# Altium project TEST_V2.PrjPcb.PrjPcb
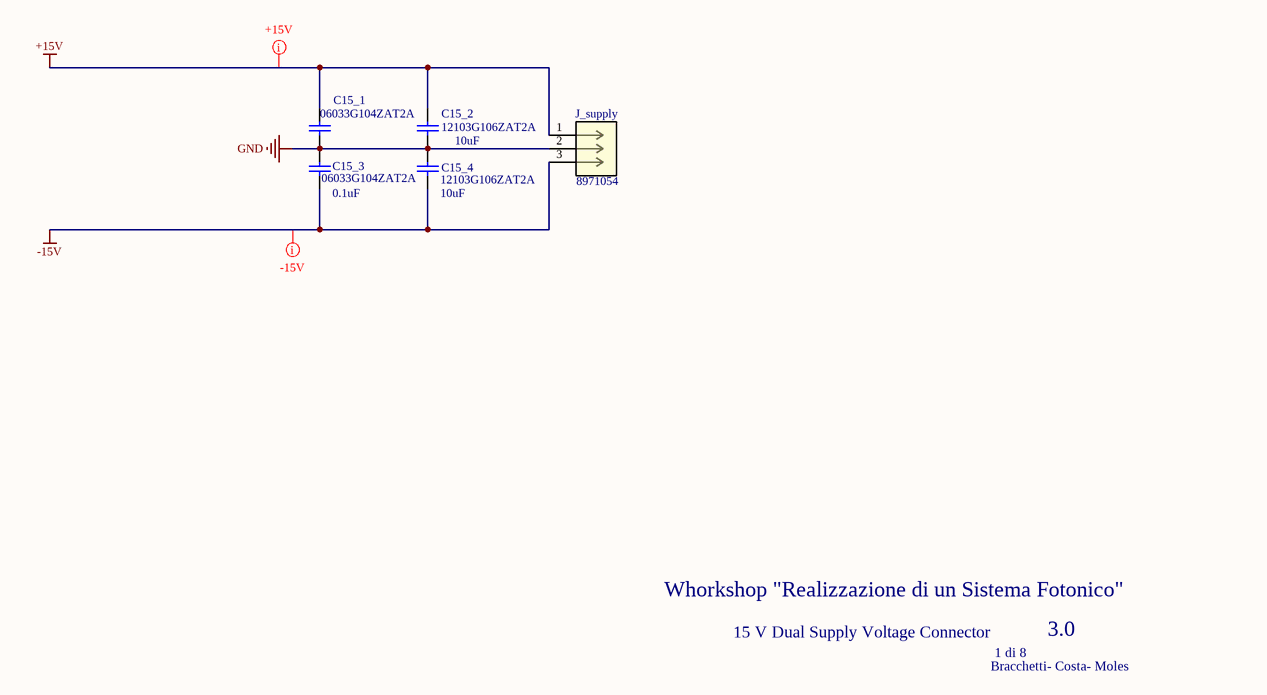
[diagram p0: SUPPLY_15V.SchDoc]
8 sheets, 172 parts. Net scope: flat (ports and power ports of the same name join across sheets).
Board file: 6C-2L-1550um.PcbDoc
Sheets:
  SUPPLY_15V.SchDoc
  SUPPLY_3V3.SchDoc
  SUPPLY_5V.SchDoc
  STAGE _1_2.SchDoc
  SWITCH_stage.SchDoc
  Selector_stage.SchDoc
  Filters.SchDoc
  OUT_STAGE.SchDoc

## Sheet SUPPLY_15V.SchDoc
size A4

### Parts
C15_1  06033G104ZAT2A  [1608[0603]]
C15_2  12103G106ZAT2A  value 10uF  [C1210_M]
C15_3  06033G104ZAT2A  value 0.1uF  [1608[0603]]
C15_4  12103G106ZAT2A  value 10uF  [C1210_M]
J_supply  8971054  [CONN_8971054_RSP]

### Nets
+15V: C15_1.2 C15_2.2 J_supply.1
-15V: C15_3.1 C15_4.1 J_supply.3
GND: C15_1.1 C15_2.1 C15_3.2 C15_4.2 J_supply.2

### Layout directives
net class +15V: +15V
net class -15V: -15V

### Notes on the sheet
- Whorkshop "Realizzazione di un Sistema Fotonico"
- 15 V Dual Supply Voltage Connector
- 1 di 8
- 3.0
- Bracchetti- Costa- Moles

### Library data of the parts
C15_1 = Cap Semi: Capacitor (Semiconductor SIM Model); Value: 0.1uF
C15_2-C15_4 = Cap Semi: Capacitor (Semiconductor SIM Model)
J_supply = 8971054: No Description Available; Built_By: EMA_Justin; Vendor: RS PRO; SourceLibrary: RS_Pro_2020-07-29

## Sheet SUPPLY_3V3.SchDoc
size A4
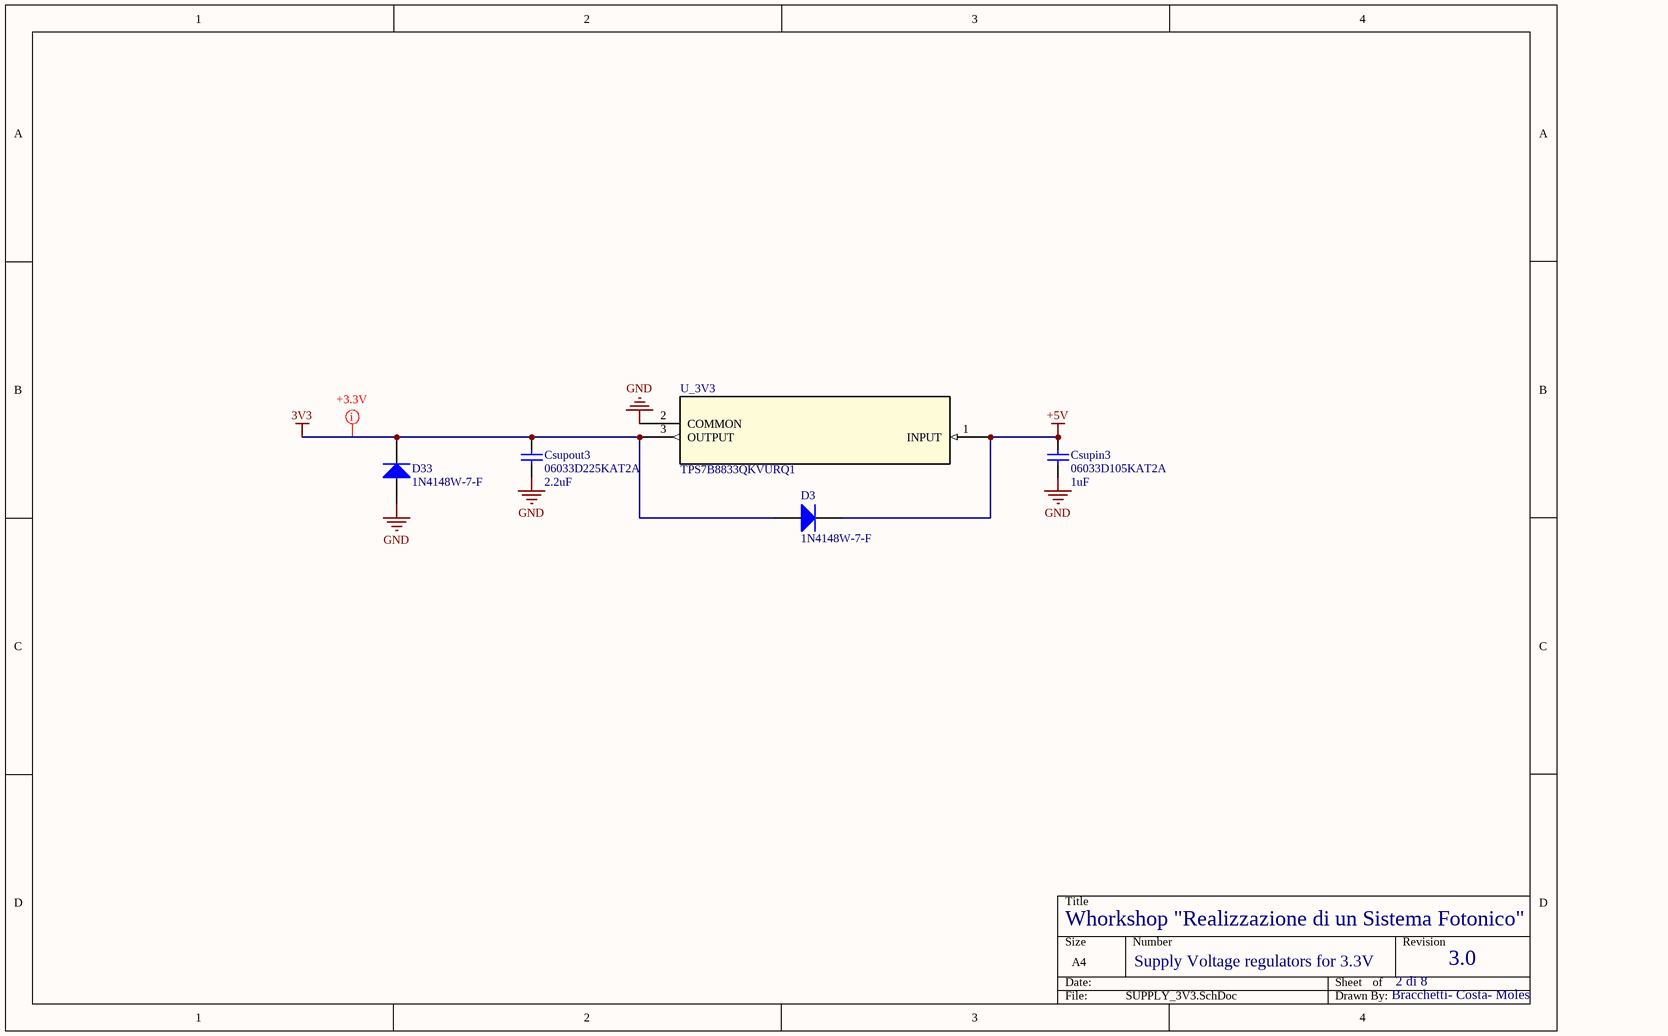
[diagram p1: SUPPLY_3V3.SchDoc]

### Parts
Csupin3  06033D105KAT2A  value 1uF  [1608[0603]]
Csupout3  06033D225KAT2A  value 2.2uF  [1608[0603]]
D3  1N4148W-7-F  [DIOD-SOD123-2_V]
D33  1N4148W-7-F  [DIOD-SOD123-2_V]
U_3V3  TPS7B8833QKVURQ1  [KVU3_TEX]

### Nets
3V3: Csupout3.2 D3.1(A) D33.2(K) U_3V3.3(OUTPUT)
+5V: Csupin3.2 D3.2(K) U_3V3.1(INPUT)
GND: Csupin3.1 Csupout3.1 D33.1(A) U_3V3.2(COMMON)

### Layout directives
net class 3.3V: 3V3

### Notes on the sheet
- Whorkshop "Realizzazione di un Sistema Fotonico"
- Supply Voltage regulators for 3.3V
- 2 di 8
- 3.0
- Bracchetti- Costa- Moles

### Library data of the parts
Csupin3 Csupout3 = Cap Semi: Capacitor (Semiconductor SIM Model)
D3 D33 = CMP-2000-04932-2: Fast Switching Diode, 100 V, 0.15 A, -65 to 150 degC, 2-Pin?SOD123, RoHS, Tape and Reel; Recovery Time: 4ns; Brand: DiodesIncorporated; Unit Weight: 0.000353oz; Max Surge Current: 2A; Peak Reverse Voltage: 100V; Ir - Reverse Current: 1uA; Vf - Forward Voltage: 1.25V; Configuration: Single; If - Forward Current: 0.15A
U_3V3 = UA78M33IKVURG3: No Description Available; Vendor: Texas Instruments; Built_By: EMA_UL_Team; SourceLibrary: TI_2016-07-22

## Sheet SUPPLY_5V.SchDoc
size A4
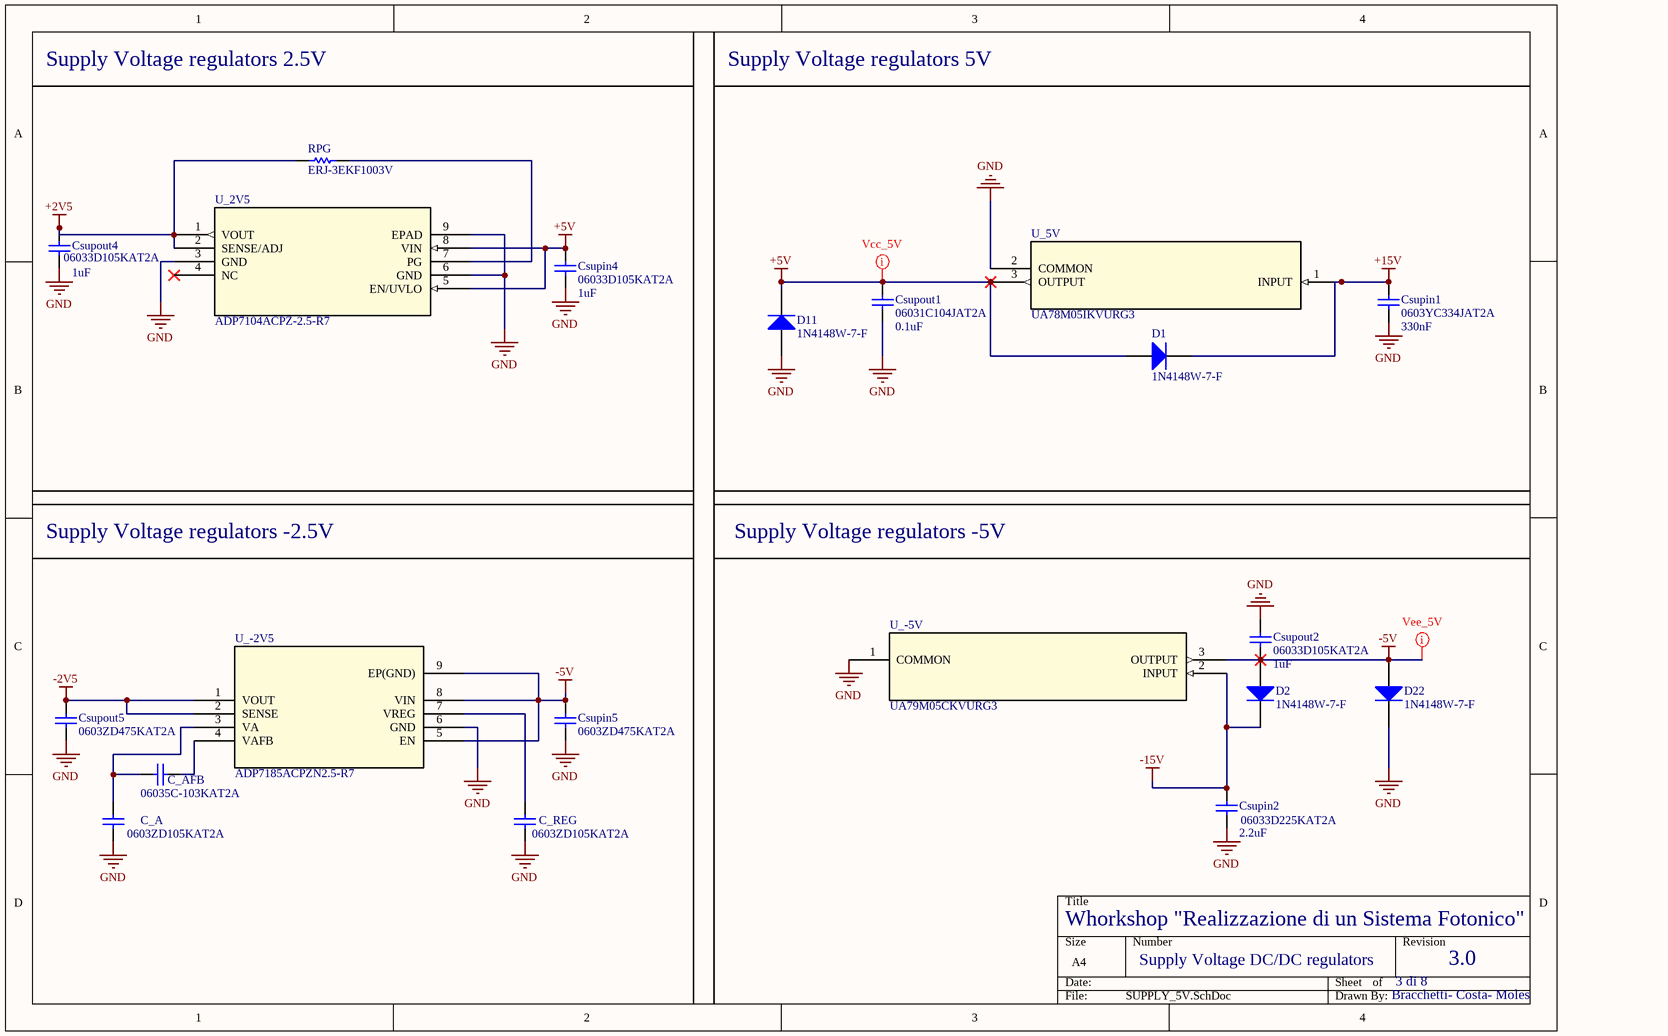
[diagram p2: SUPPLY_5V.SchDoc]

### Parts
C_A  0603ZD105KAT2A  [CAPC1608X86X35LL15T15]
C_AFB  06035C-103KAT2A  [CAPC1608X90X35LL15T15]
C_REG  0603ZD105KAT2A  [CAPC1608X86X35LL15T15]
Csupin1  0603YC334JAT2A  value 330nF  [1608[0603]]
Csupin2  06033D225KAT2A  value 2.2uF  [1608[0603]]
Csupin4  06033D105KAT2A  value 1uF  [1608[0603]]
Csupin5  0603ZD475KAT2A  [CAPC1608X90X35NL15T15]
Csupout1  06031C104JAT2A  value 0.1uF  [1608[0603]]
Csupout2  06033D105KAT2A  value 1uF  [1608[0603]]
Csupout4  06033D105KAT2A  value 1uF  [1608[0603]]
Csupout5  0603ZD475KAT2A  [CAPC1608X90X35NL15T15]
D1  1N4148W-7-F  [DIOD-SOD123-2_V]
D2  1N4148W-7-F  [DIOD-SOD123-2_V]
D11  1N4148W-7-F  [DIOD-SOD123-2_V]
D22  1N4148W-7-F  [DIOD-SOD123-2_V]
RPG  ERJ-3EKF1003V  [RESC1608X55X30ML15T15]
U_2V5  ADP7104ACPZ-2.5-R7  [CP_8_5_ADI]
U_5V  UA78M05IKVURG3  [KVU3_TEX]
U_-2V5  ADP7185ACPZN2.5-R7  [CP_8_27_ADI]
U_-5V  UA79M05CKVURG3  [KVU3_TEX]

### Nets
+2V5: Csupout4.2 RPG.2 U_2V5.1(VOUT) U_2V5.2(SENSE/ADJ)
+5V: Csupin4.2 Csupout1.2 D1.1(A) D11.2(K) U_2V5.5(EN/UVLO) U_2V5.8(VIN) U_5V.3(OUTPUT)
+15V: Csupin1.2 D1.2(K) U_5V.1(INPUT)
-2V5: Csupout5.2 U_-2V5.1(VOUT) U_-2V5.2(SENSE)
-5V: Csupin5.2 Csupout2.1 D2.1(A) D22.1(A) U_-2V5.5(EN) U_-2V5.8(VIN) U_-2V5.9(EP(GND)) U_-5V.3(OUTPUT)
-15V: Csupin2.2 D2.2(K) U_-5V.2(INPUT)
GND: C_A.1 C_REG.1 Csupin1.1 Csupin2.1 Csupin4.1 Csupin5.1 Csupout1.1 Csupout2.2 Csupout4.1 Csupout5.1 D11.1(A) D22.2(K) U_2V5.3(GND) U_2V5.6(GND) U_2V5.9(EPAD) U_5V.2(COMMON) U_-2V5.6(GND) U_-5V.1(COMMON)
NetC_A_2: C_A.2 C_AFB.2 U_-2V5.3(VA)
NetC_AFB_1: C_AFB.1 U_-2V5.4(VAFB)
NetC_REG_2: C_REG.2 U_-2V5.7(VREG)
NetRPG_1: RPG.1 U_2V5.7(PG)

Not connected (* = marked no-connect by the designer): U_2V5 4(NC)*

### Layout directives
net class +5V: +5V
net class -5V: -5V

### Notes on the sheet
- Supply Voltage regulators 2.5V
- Supply Voltage regulators 5V
- Supply Voltage regulators -2.5V
- Supply Voltage regulators -5V
- Whorkshop "Realizzazione di un Sistema Fotonico"
- Supply Voltage DC/DC regulators
- 3 di 8
- 3.0
- Bracchetti- Costa- Moles

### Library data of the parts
C_A C_REG = CMP-2006-04559-2: Chip Capacitor, 1 uF, +/- 10%, 10 V, -55 to 85 degC, 0603 (1608 Metric), RoHS, Tape and Reel; Manufacturer: AVX; Rated Voltage: 10V; Capacitance: 1µF; Dielectric: X5R
C_AFB = CMP-2006-04374-1: Manufacturer: AVX Interconnect / Elco
Csupin1 Csupin2 Csupin4 Csupout1 Csupout2 Csupout4 = Cap Semi: Capacitor (Semiconductor SIM Model)
Csupin5 Csupout5 = CMP-2006-04567-1: Manufacturer: AVX Interconnect / Elco
D1 D2 D11 D22 = CMP-2000-04932-2: as D3 on sheet SUPPLY_3V3
RPG = CMP-2000-00182-1: Manufacturer: Panasonic
U_2V5 = ADP7104ACPZ-2.5-R7: No Description Available; Vendor: Analog Devices Inc; Built_By: EMA_Christopher; SourceLibrary: Analog_Devices_2018-07-13
U_5V = UA78M05IKVURG3: No Description Available; Vendor: Texas Instruments; Built_By: EMA_UL_Team; SourceLibrary: TI_2016-07-22
U_-2V5 = ADP7185ACPZN2.5-R7: No Description Available; Vendor: Analog Devices Inc; Built_By: Analog Devices Inc.; SourceLibrary: Analog_2017-10-24
U_-5V = UA79M05CKVURG3: No Description Available; Vendor: Texas Instruments; Built_By: EMA_UL_Team; SourceLibrary: TI_2015-1-6

## Sheet STAGE _1_2.SchDoc
size A4
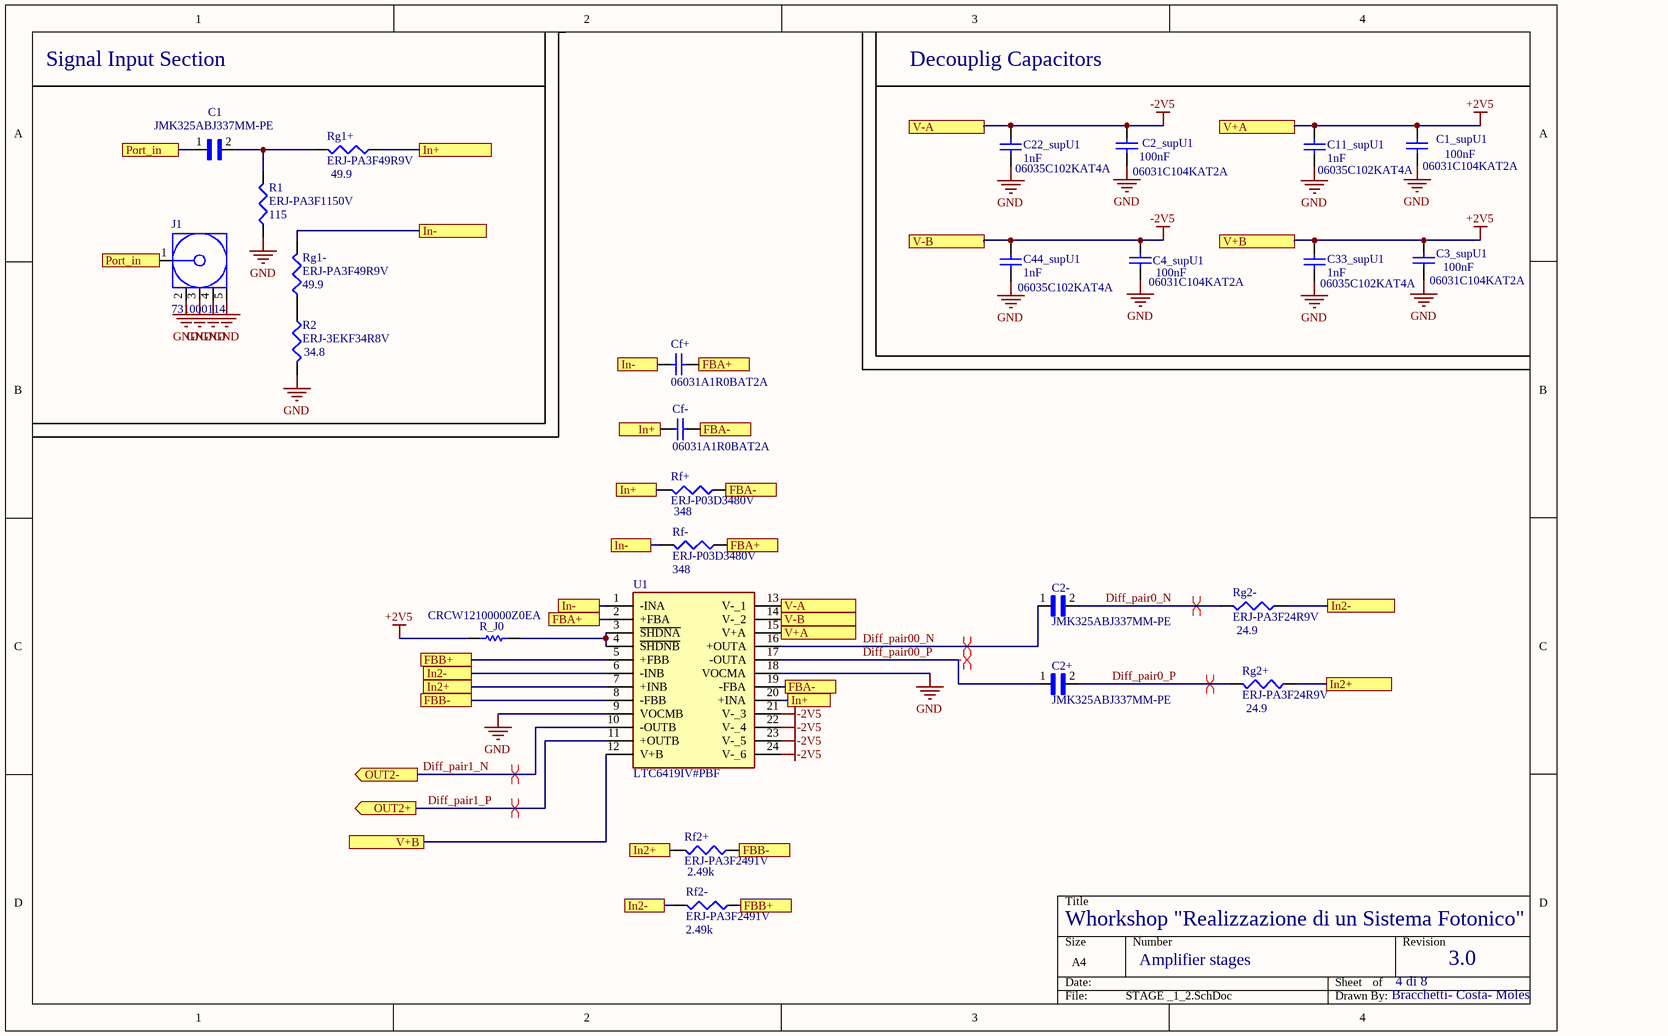
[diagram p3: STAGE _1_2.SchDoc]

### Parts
C1  JMK325ABJ337MM-PE  [CAPC3225X280N]
C1_supU1  06031C104KAT2A  value 100nF  [1608[0603]]
C2+  JMK325ABJ337MM-PE  [CAPC3225X280N]
C2-  JMK325ABJ337MM-PE  [CAPC3225X280N]
C2_supU1  06031C104KAT2A  value 100nF  [1608[0603]]
C3_supU1  06031C104KAT2A  value 100nF  [1608[0603]]
C4_supU1  06031C104KAT2A  value 100nF  [1608[0603]]
C11_supU1  06035C102KAT4A  value 1nF  [1608[0603]]
C22_supU1  06035C102KAT4A  value 1nF  [1608[0603]]
C33_supU1  06035C102KAT4A  value 1nF  [1608[0603]]
C44_supU1  06035C102KAT4A  value 1nF  [1608[0603]]
Cf+  06031A1R0BAT2A  [CAPC1608X90X35LL15T15]
Cf-  06031A1R0BAT2A  [CAPC1608X90X35LL15T15]
J1  731000114  [MOLX-731000114_V]
R1  ERJ-PA3F1150V  value 115  [1608[0603]]
R2  ERJ-3EKF34R8V  value 34.8  [1608[0603]]
R_J0  CRCW12100000Z0EA  [RESC3225X60X45NL20T20]
Rf2+  ERJ-PA3F2491V  value 2.49k  [1608[0603]]
Rf2-  ERJ-PA3F2491V  value 2.49k  [1608[0603]]
Rf+  ERJ-P03D3480V  value 348  [1608[0603]]
Rf-  ERJ-P03D3480V  value 348  [1608[0603]]
Rg1+  ERJ-PA3F49R9V  value 49.9  [1608[0603]]
Rg1-  ERJ-PA3F49R9V  value 49.9  [1608[0603]]
Rg2+  ERJ-PA3F24R9V  value 24.9  [1608[0603]]
Rg2-  ERJ-PA3F24R9V  value 24.9  [1608[0603]]
U1  LTC6419IV#PBF  [LTC6419IVPBF]

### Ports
FBA+, FBA-, FBB+, FBB-, In2+, In2-, In+, In-, OUT2+ (out), OUT2- (out), Port_in, V+A, V+B, V-A, V-B

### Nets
+2V5: C1_supU1.1 C3_supU1.1 C11_supU1.1 C33_supU1.1 R_J0.1 U1.12(V+B) U1.15(V+A) ; port V+A, port V+B
-2V5: C2_supU1.1 C4_supU1.1 C22_supU1.1 C44_supU1.1 U1.13(V-_1) U1.14(V-_2) U1.21(V-_3) U1.22(V-_4) U1.23(V-_5) U1.24(V-_6) ; port V-A, port V-B
GND: C1_supU1.2 C2_supU1.2 C3_supU1.2 C4_supU1.2 C11_supU1.2 C22_supU1.2 C33_supU1.2 C44_supU1.2 J1.2 J1.3 J1.4 J1.5 R1.1 R2.2 U1.9(VOCMB) U1.18(VOCMA)
Diff_pair0_N: C2-.2 Rg2-.2
Diff_pair00_N: C2-.1 U1.16(+OUTA)
Diff_pair0_P: C2+.2 Rg2+.2
Diff_pair00_P: C2+.1 U1.17(-OUTA)
Diff_pair1_N: U1.10(-OUTB) ; port OUT2-
Diff_pair1_P: U1.11(+OUTB) ; port OUT2+
NetC1_1: C1.1 J1.1 ; port Port_in
NetC1_2: C1.2 R1.2 Rg1+.2
NetCf+_1: Cf+.1 Rf-.2 Rg1-.2 U1.1(-INA) ; port In-
NetCf+_2: Cf+.2 Rf-.1 U1.2(+FBA) ; port FBA+
NetCf-_1: Cf-.1 Rf+.2 Rg1+.1 U1.20(+INA) ; port In+
NetCf-_2: Cf-.2 Rf+.1 U1.19(-FBA) ; port FBA-
NetR2_1: R2.1 Rg1-.1
NetR_J0_2: R_J0.2 U1.3(~{SHDNA}) U1.4(~{SHDNB})
NetRf2+_1: Rf2+.1 U1.8(-FBB) ; port FBB-
NetRf2+_2: Rf2+.2 Rg2+.1 U1.7(+INB) ; port In2+
NetRf2-_1: Rf2-.1 U1.5(+FBB) ; port FBB+
NetRf2-_2: Rf2-.2 Rg2-.1 U1.6(-INB) ; port In2-

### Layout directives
differential pair: Diff_pair0_N, Diff_pair00_N, Diff_pair00_P, Diff_pair0_P, Diff_pair1_N, Diff_pair1_P

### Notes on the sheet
- Signal Input Section
- Decouplig Capacitors
- Whorkshop "Realizzazione di un Sistema Fotonico"
- Amplifier stages
- 4 di 8
- 3.0
- Bracchetti- Costa- Moles

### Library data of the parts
C1 C2+ C2- = JMK325ABJ337MM-PE: 330ÂµF Â±20% 6.3V Ceramic Capacitor X5R 1210 (3225 Metric); MF: Taiyo Yuden
C1_supU1 C2_supU1 C3_supU1 C4_supU1 C11_supU1 C22_supU1 C33_supU1 C44_supU1 = Cap Semi: Capacitor (Semiconductor SIM Model)
Cf+ Cf- = CMP-2006-04007-1: Manufacturer: AVX Interconnect / Elco
J1 = CMP-2000-05487-1: SMA Right-Angle PCB Jack Receptacle, Brass Body, Gold Plated, 50 Ohm, 5-Pin THD, RoHS, Tray; Manufacturer: Molex
R1 R2 Rf2+ Rf2- Rf+ Rf- Rg1+ Rg1- Rg2+ Rg2- = Res3: Resistor
R_J0 = CMP-2005-01987-1: Manufacturer: Vishay Dale
U1 = LTC6419IV#PBF: Integrated Circuit; Manufacturer_Name: Analog Devices

## Sheet SWITCH_stage.SchDoc
size A4
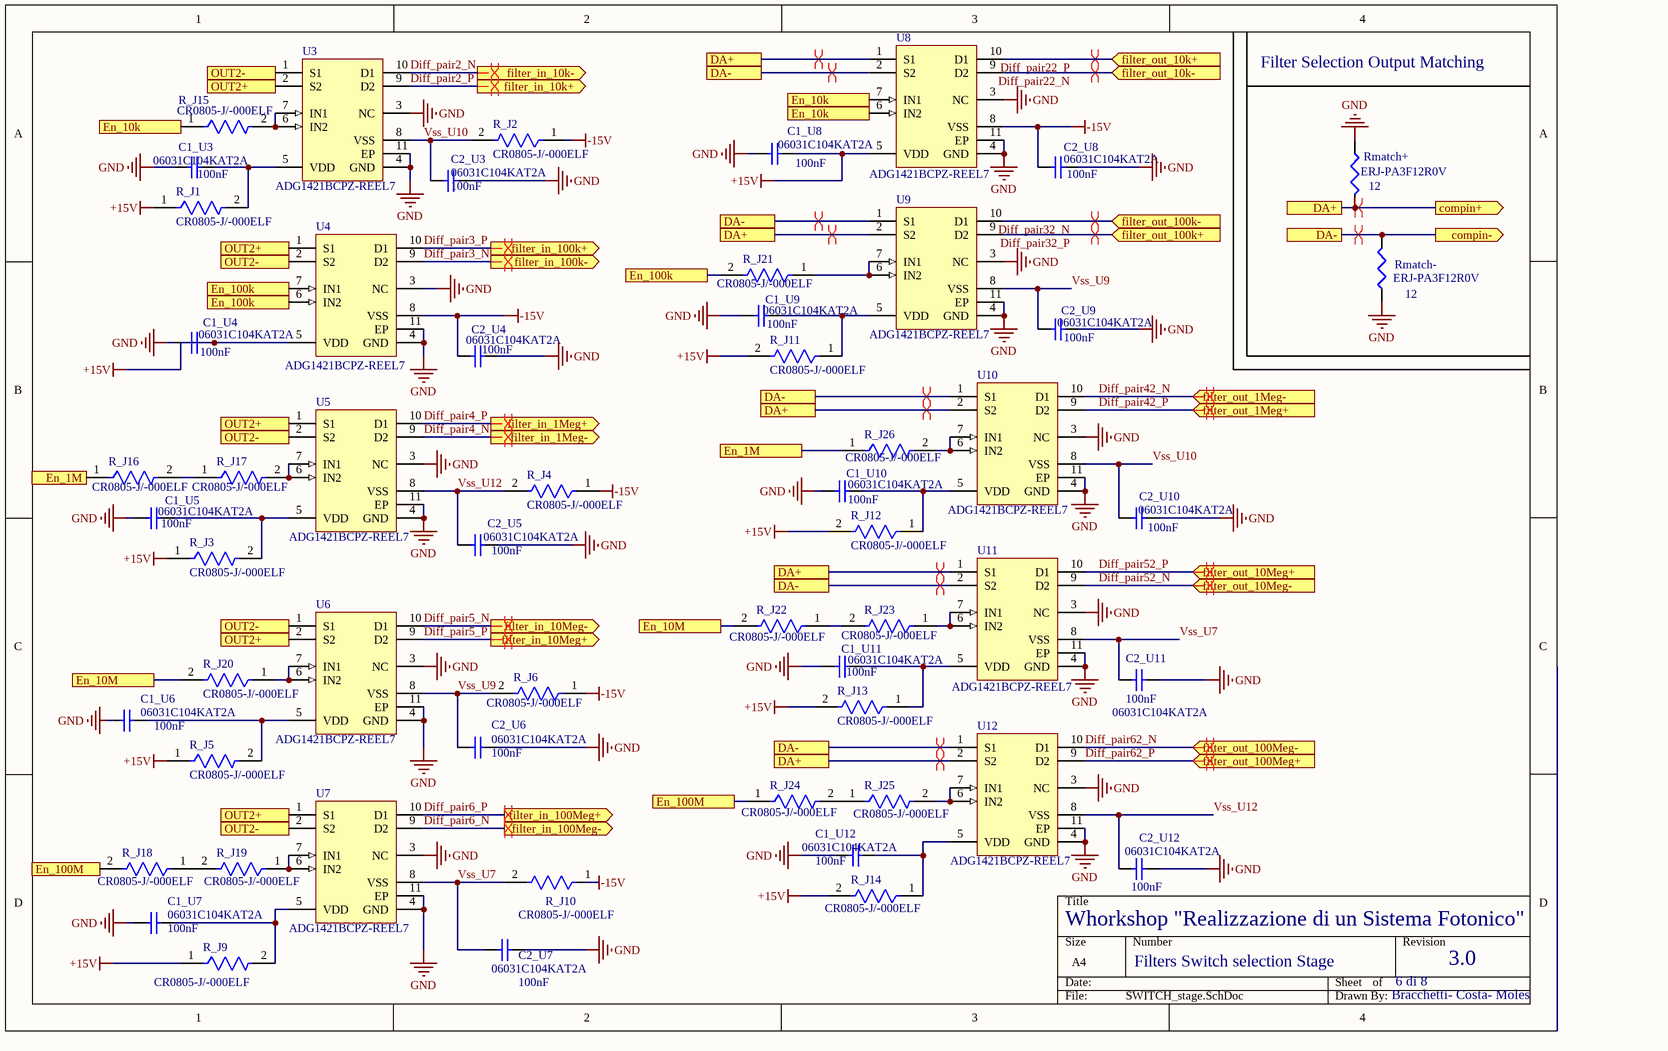
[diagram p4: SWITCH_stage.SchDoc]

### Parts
C1_U3  06031C104KAT2A  value 100nF  [1608[0603]]
C1_U4  06031C104KAT2A  value 100nF  [1608[0603]]
C1_U5  06031C104KAT2A  value 100nF  [1608[0603]]
C1_U6  06031C104KAT2A  value 100nF  [1608[0603]]
C1_U7  06031C104KAT2A  value 100nF  [1608[0603]]
C1_U8  06031C104KAT2A  value 100nF  [1608[0603]]
C1_U9  06031C104KAT2A  value 100nF  [1608[0603]]
C1_U10  06031C104KAT2A  value 100nF  [1608[0603]]
C1_U11  06031C104KAT2A  value 100nF  [1608[0603]]
C1_U12  06031C104KAT2A  value 100nF  [1608[0603]]
C2_U3  06031C104KAT2A  value 100nF  [1608[0603]]
C2_U4  06031C104KAT2A  value 100nF  [1608[0603]]
C2_U5  06031C104KAT2A  value 100nF  [1608[0603]]
C2_U6  06031C104KAT2A  value 100nF  [1608[0603]]
C2_U7  06031C104KAT2A  value 100nF  [1608[0603]]
C2_U8  06031C104KAT2A  value 100nF  [1608[0603]]
C2_U9  06031C104KAT2A  value 100nF  [1608[0603]]
C2_U10  06031C104KAT2A  value 100nF  [1608[0603]]
C2_U11  06031C104KAT2A  value 100nF  [1608[0603]]
C2_U12  06031C104KAT2A  value 100nF  [1608[0603]]
R_J1  CR0805-J/-000ELF  [FP-CR0805-MFG]
R_J2  CR0805-J/-000ELF  [FP-CR0805-MFG]
R_J3  CR0805-J/-000ELF  [FP-CR0805-MFG]
R_J4  CR0805-J/-000ELF  [FP-CR0805-MFG]
R_J5  CR0805-J/-000ELF  [FP-CR0805-MFG]
R_J6  CR0805-J/-000ELF  [FP-CR0805-MFG]
R_J9  CR0805-J/-000ELF  [FP-CR0805-MFG]
R_J10  CR0805-J/-000ELF  [FP-CR0805-MFG]
R_J11  CR0805-J/-000ELF  [FP-CR0805-MFG]
R_J12  CR0805-J/-000ELF  [FP-CR0805-MFG]
R_J13  CR0805-J/-000ELF  [FP-CR0805-MFG]
R_J14  CR0805-J/-000ELF  [FP-CR0805-MFG]
R_J15  CR0805-J/-000ELF  [FP-CR0805-MFG]
R_J16  CR0805-J/-000ELF  [FP-CR0805-MFG]
R_J17  CR0805-J/-000ELF  [FP-CR0805-MFG]
R_J18  CR0805-J/-000ELF  [FP-CR0805-MFG]
R_J19  CR0805-J/-000ELF  [FP-CR0805-MFG]
R_J20  CR0805-J/-000ELF  [FP-CR0805-MFG]
R_J21  CR0805-J/-000ELF  [FP-CR0805-MFG]
R_J22  CR0805-J/-000ELF  [FP-CR0805-MFG]
R_J23  CR0805-J/-000ELF  [FP-CR0805-MFG]
R_J24  CR0805-J/-000ELF  [FP-CR0805-MFG]
R_J25  CR0805-J/-000ELF  [FP-CR0805-MFG]
R_J26  CR0805-J/-000ELF  [FP-CR0805-MFG]
Rmatch+  ERJ-PA3F12R0V  value 12  [1608[0603]]
Rmatch-  ERJ-PA3F12R0V  value 12  [1608[0603]]
U3  ADG1421BCPZ-REEL7  [ADI-CP-10-9_V]
U4  ADG1421BCPZ-REEL7  [ADI-CP-10-9_V]
U5  ADG1421BCPZ-REEL7  [ADI-CP-10-9_V]
U6  ADG1421BCPZ-REEL7  [ADI-CP-10-9_V]
U7  ADG1421BCPZ-REEL7  [ADI-CP-10-9_V]
U8  ADG1421BCPZ-REEL7  [ADI-CP-10-9_V]
U9  ADG1421BCPZ-REEL7  [ADI-CP-10-9_V]
U10  ADG1421BCPZ-REEL7  [ADI-CP-10-9_V]
U11  ADG1421BCPZ-REEL7  [ADI-CP-10-9_V]
U12  ADG1421BCPZ-REEL7  [ADI-CP-10-9_V]

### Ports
compin+ (out), compin- (out), DA+, DA-, En_1M, En_10k, En_10M, En_100k, En_100M, filter_in_1Meg+ (out), filter_in_1Meg- (out), filter_in_10k+ (out), filter_in_10k- (out), filter_in_10Meg+ (out), filter_in_10Meg- (out), filter_in_100k+ (out), filter_in_100k- (out), filter_in_100Meg+ (out), filter_in_100Meg- (out), filter_out_1Meg+ (in), filter_out_1Meg- (in), filter_out_10k+ (in), filter_out_10k- (in), filter_out_10Meg+ (in), filter_out_10Meg- (in), filter_out_100k+ (in), filter_out_100k- (in), filter_out_100Meg+ (in), filter_out_100Meg- (in), OUT2+, OUT2-

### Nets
+15V: C1_U4.2 C1_U8.2 R_J1.1 R_J3.1 R_J5.1 R_J9.1 R_J11.2 R_J12.2 R_J13.2 R_J14.2 U4.5(VDD) U8.5(VDD)
-15V: C2_U4.2 C2_U8.2 R_J2.1 R_J4.1 R_J6.1 R_J10.1 U4.8(VSS) U8.8(VSS)
GND: C1_U3.1 C1_U4.1 C1_U5.1 C1_U6.1 C1_U7.1 C1_U8.1 C1_U9.1 C1_U10.1 C1_U11.1 C1_U12.1 C2_U3.1 C2_U4.1 C2_U5.1 C2_U6.1 C2_U7.1 C2_U8.1 C2_U9.1 C2_U10.1 C2_U11.1 C2_U12.1 Rmatch+.1 Rmatch-.1 U3.3(NC) U3.4(GND) U3.11(EP) U4.3(NC) U4.4(GND) U4.11(EP) U5.3(NC) U5.4(GND) U5.11(EP) U6.3(NC) U6.4(GND) U6.11(EP) U7.3(NC) U7.4(GND) U7.11(EP) U8.3(NC) U8.4(GND) U8.11(EP) U9.3(NC) U9.4(GND) U9.11(EP) U10.3(NC) U10.4(GND) U10.11(EP) U11.3(NC) U11.4(GND) U11.11(EP) U12.3(NC) U12.4(GND) U12.11(EP)
Diff_pair1_N: U3.1(S1) U4.2(S2) U5.2(S2) U6.1(S1) U7.2(S2) ; port OUT2-
Diff_pair1_P: U3.2(S2) U4.1(S1) U5.1(S1) U6.2(S2) U7.1(S1) ; port OUT2+
Diff_pair2_N: U3.10(D1) ; port filter_in_10k-
Diff_pair2_P: U3.9(D2) ; port filter_in_10k+
Diff_pair3_N: U4.9(D2) ; port filter_in_100k-
Diff_pair3_P: U4.10(D1) ; port filter_in_100k+
Diff_pair4_N: U5.9(D2) ; port filter_in_1Meg-
Diff_pair4_P: U5.10(D1) ; port filter_in_1Meg+
Diff_pair5_N: U6.10(D1) ; port filter_in_10Meg-
Diff_pair5_P: U6.9(D2) ; port filter_in_10Meg+
Diff_pair6_N: U7.9(D2) ; port filter_in_100Meg-
Diff_pair6_P: U7.10(D1) ; port filter_in_100Meg+
Diff_Pair9_N: Rmatch-.2 U8.2(S2) U9.1(S1) U10.1(S1) U11.2(S2) U12.1(S1) ; port compin-, port DA-
Diff_Pair9_P: Rmatch+.2 U8.1(S1) U9.2(S2) U10.2(S2) U11.1(S1) U12.2(S2) ; port compin+, port DA+
Diff_pair22_N: U8.9(D2) ; port filter_out_10k-  [project net Diff_pair21_P]
Diff_pair22_P: U8.10(D1) ; port filter_out_10k+  [project net Diff_pair21_N]
Diff_pair32_N: U9.10(D1) ; port filter_out_100k-  [project net Diff_pair31_N]
Diff_pair32_P: U9.9(D2) ; port filter_out_100k+  [project net Diff_pair31_P]
Diff_pair42_N: U10.10(D1) ; port filter_out_1Meg-  [project net Diff_pair41_N]
Diff_pair42_P: U10.9(D2) ; port filter_out_1Meg+  [project net Diff_pair41_P]
Diff_pair52_N: U11.9(D2) ; port filter_out_10Meg-  [project net Diff_pair51_P]
Diff_pair52_P: U11.10(D1) ; port filter_out_10Meg+  [project net Diff_pair51_N]
Diff_pair62_N: U12.10(D1) ; port filter_out_100Meg-  [project net Diff_pair61_N]
Diff_pair62_P: U12.9(D2) ; port filter_out_100Meg+  [project net Diff_pair61_P]
Vss_U7: C2_U7.2 C2_U11.2 R_J10.2 U7.8(VSS) U11.8(VSS)
Vss_U9: C2_U6.2 C2_U9.2 R_J6.2 U6.8(VSS) U9.8(VSS)
Vss_U10: C2_U3.2 C2_U10.2 R_J2.2 U3.8(VSS) U10.8(VSS)
Vss_U12: C2_U5.2 C2_U12.2 R_J4.2 U5.8(VSS) U12.8(VSS)
NetC1_U3_2: C1_U3.2 R_J1.2 U3.5(VDD)
NetC1_U5_2: C1_U5.2 R_J3.2 U5.5(VDD)
NetC1_U6_2: C1_U6.2 R_J5.2 U6.5(VDD)
NetC1_U7_2: C1_U7.2 R_J9.2 U7.5(VDD)
NetC1_U9_2: C1_U9.2 R_J11.1 U9.5(VDD)
NetC1_U10_2: C1_U10.2 R_J12.1 U10.5(VDD)
NetC1_U11_2: C1_U11.2 R_J13.1 U11.5(VDD)
NetC1_U12_2: C1_U12.2 R_J14.1 U12.5(VDD)
NetR_J15_1: R_J15.1 U8.6(IN2) U8.7(IN1) ; port En_10k
NetR_J15_2: R_J15.2 U3.6(IN2) U3.7(IN1)
NetR_J16_1: R_J16.1 R_J26.1 ; port En_1M
NetR_J16_2: R_J16.2 R_J17.1
NetR_J17_2: R_J17.2 U5.6(IN2) U5.7(IN1)
NetR_J18_1: R_J18.1 R_J19.2
NetR_J18_2: R_J18.2 R_J24.1 ; port En_100M
NetR_J19_1: R_J19.1 U7.6(IN2) U7.7(IN1)
NetR_J20_1: R_J20.1 U6.6(IN2) U6.7(IN1)
NetR_J20_2: R_J20.2 R_J22.2 ; port En_10M
NetR_J21_1: R_J21.1 U9.6(IN2) U9.7(IN1)
NetR_J21_2: R_J21.2 U4.6(IN2) U4.7(IN1) ; port En_100k
NetR_J22_1: R_J22.1 R_J23.2
NetR_J23_1: R_J23.1 U11.6(IN2) U11.7(IN1)
NetR_J24_2: R_J24.2 R_J25.1
NetR_J25_2: R_J25.2 U12.6(IN2) U12.7(IN1)
NetR_J26_2: R_J26.2 U10.6(IN2) U10.7(IN1)

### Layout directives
differential pair: Diff_pair2_N, Diff_pair2_P, Diff_pair3_N, Diff_pair3_P, Diff_pair4_N, Diff_pair4_P, Diff_pair5_N, Diff_pair5_P, Diff_pair6_N, Diff_pair6_P, Diff_Pair9_N, Diff_Pair9_P, Diff_pair21_N, Diff_pair21_P, Diff_pair31_N, Diff_pair31_P, Diff_pair41_N, Diff_pair41_P, Diff_pair51_N, Diff_pair51_P, Diff_pair61_N, Diff_pair61_P

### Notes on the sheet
- Filter Selection Output Matching
- (near C2_U12) Whorkshop "Realizzazione di un Sistema Fotonico"
- Filters Switch selection Stage
- 6 di 8
- 3.0
- Bracchetti- Costa- Moles

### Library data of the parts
C1_U3-C1_U12 C2_U3-C2_U12 = Cap Semi: Capacitor (Semiconductor SIM Model)
R_J1-R_J6 R_J9-R_J26 = CMP-07231-004348-1: Thick Film Chip Resistors 0805 0Ω 0.125W 5%; Voltage Rating: 150V; Max Power Dissipation: 125mW; Temperature Coefficient: 500ppm/°C; Resistance: 0mR
Rmatch+ Rmatch- = Res3: Resistor
U3-U12 = CMP-0790-00013-1: 2.1 Ohm On Resistance, +/-15 V / +12 V / +/-5 V iCMOS Dual SPST Switch, -40 to 125 degC, 10-pin SON (CP-10-9), Reel; Manufacturer: Analog Devices; Power Dissipation: 1.8mW; Is OFF: 100pA, 50pA, 50pA; Ron (ohms): 2.1; Id, Is (ON): 200pA, 100pA, 100pA

## Sheet Selector_stage.SchDoc
size A4
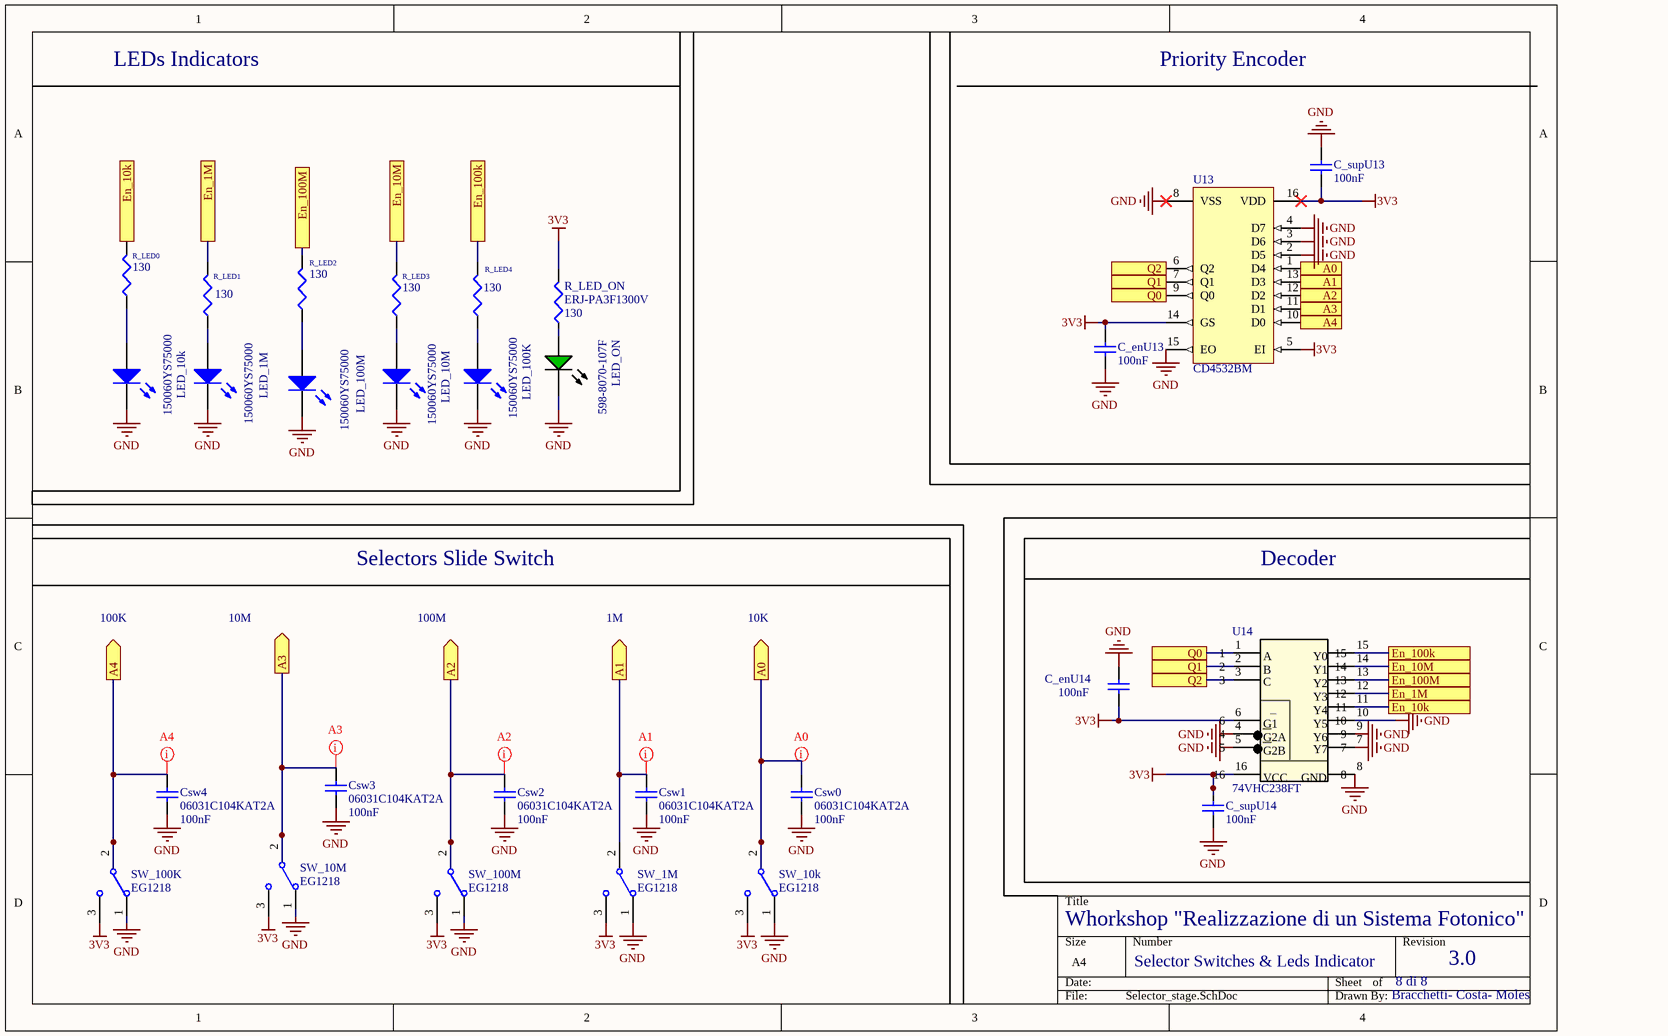
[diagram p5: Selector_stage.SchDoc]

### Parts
C_enU13  value 100nF  [1608[0603]]  (hidden comment: 06031C104KAT2A)
C_enU14  value 100nF  [1608[0603]]  (hidden comment: 06031C104KAT2A)
C_supU13  value 100nF  [1608[0603]]  (hidden comment: 06031C104KAT2A)
C_supU14  value 100nF  [1608[0603]]  (hidden comment: 06031C104KAT2A)
Csw0  06031C104KAT2A  value 100nF  [1608[0603]]
Csw1  06031C104KAT2A  value 100nF  [1608[0603]]
Csw2  06031C104KAT2A  value 100nF  [1608[0603]]
Csw3  06031C104KAT2A  value 100nF  [1608[0603]]
Csw4  06031C104KAT2A  value 100nF  [1608[0603]]
LED_1M  150060YS75000  [0603_A]
LED_10k  150060YS75000  [0603_A]
LED_10M  150060YS75000  [0603_A]
LED_100K  150060YS75000  [0603_A]
LED_100M  150060YS75000  [0603_A]
LED_ON  598-8070-107F  [DIAL-0603-2_V]
R_LED0  value 130  [1608[0603]]  (hidden comment: ERJ-PA3F1300V)
R_LED1  value 130  [1608[0603]]  (hidden comment: ERJ-PA3F1300V)
R_LED2  value 130  [1608[0603]]  (hidden comment: ERJ-PA3F1300V)
R_LED3  value 130  [1608[0603]]  (hidden comment: ERJ-PA3F1300V)
R_LED4  value 130  [1608[0603]]  (hidden comment: ERJ-PA3F1300V)
R_LED_ON  ERJ-PA3F1300V  value 130  [1608[0603]]
SW_1M  EG1218  [ESWI-EG1218_V]
SW_10k  EG1218  [ESWI-EG1218_V]
SW_10M  EG1218  [ESWI-EG1218_V]
SW_100K  EG1218  [ESWI-EG1218_V]
SW_100M  EG1218  [ESWI-EG1218_V]
U13  CD4532BM  [D0016A_M]
U14  74VHC238FT  [TSSOP16B]

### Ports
A0, A0 (out), A1, A1 (out), A2, A2 (out), A3, A3 (out), A4, A4 (out), En_1M, En_10k, En_10M, En_100k, En_100M, Q0, Q1, Q2

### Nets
3V3: C_enU13.1 C_enU14.1 C_supU13.1 C_supU14.1 R_LED_ON.2 SW_1M.3 SW_10k.3 SW_10M.3 SW_100K.3 SW_100M.3 U13.5(EI) U13.14(GS) U13.16(VDD) U14.6 U14.16
GND: C_enU13.2 C_enU14.2 C_supU13.2 C_supU14.2 Csw0.1 Csw1.1 Csw2.1 Csw3.1 Csw4.1 LED_1M.1(K) LED_10k.1(K) LED_10M.1(K) LED_100K.1(K) LED_100M.1(K) LED_ON.1(K) SW_1M.1 SW_10k.1 SW_10M.1 SW_100K.1 SW_100M.1 U13.2(D5) U13.3(D6) U13.4(D7) U13.8(VSS) U13.15(EO) U14.4 U14.5 U14.7 U14.8 U14.9 U14.10
NetCsw0_2: Csw0.2 SW_10k.2(COM) U13.1(D4) ; port A0
NetCsw1_2: Csw1.2 SW_1M.2(COM) U13.13(D3) ; port A1
NetCsw2_2: Csw2.2 SW_100M.2(COM) U13.12(D2) ; port A2
NetCsw3_2: Csw3.2 SW_10M.2(COM) U13.11(D1) ; port A3
NetCsw4_2: Csw4.2 SW_100K.2(COM) U13.10(D0) ; port A4
NetLED_1M_2: LED_1M.2(A) R_LED1.1
NetLED_10k_2: LED_10k.2(A) R_LED0.1
NetLED_10M_2: LED_10M.2(A) R_LED3.1
NetLED_100K_2: LED_100K.2(A) R_LED4.1
NetLED_100M_2: LED_100M.2(A) R_LED2.1
NetLED_ON_2: LED_ON.2(A) R_LED_ON.1
NetR_J15_1: R_LED0.2 U14.11 ; port En_10k
NetR_J16_1: R_LED1.2 U14.12 ; port En_1M
NetR_J18_2: R_LED2.2 U14.13 ; port En_100M
NetR_J20_2: R_LED3.2 U14.14 ; port En_10M
NetR_J21_2: R_LED4.2 U14.15 ; port En_100k
NetU13_6: U13.6(Q2) U14.3 ; port Q2
NetU13_7: U13.7(Q1) U14.2 ; port Q1
NetU13_9: U13.9(Q0) U14.1 ; port Q0

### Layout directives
mark named A2: NetCsw2_2
mark named A1: NetCsw1_2
mark named A0: NetCsw0_2
mark named A3: NetCsw3_2
mark named A4: NetCsw4_2

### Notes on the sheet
- LEDs Indicators
- Priority Encoder
- Selectors Slide Switch
- Decoder
- 100K
- 10M
- 100M
- 1M
- 10K
- Whorkshop "Realizzazione di un Sistema Fotonico"
- Selector Switches & Leds Indicator
- 8 di 8
- 3.0
- Bracchetti- Costa- Moles

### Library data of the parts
C_enU13 C_enU14 C_supU13 C_supU14 = Cap Semi: Capacitor (Semiconductor SIM Model)
Csw0-Csw4 = Cap: Capacitor
LED_1M LED_10k LED_10M LED_100K LED_100M = CMP-1426-00005-1: SMD mono-color Chip LED, WL-SMCW, Yellow; Manufacturer: Wuerth Elektronik
LED_ON = CMP-2000-05654-1: Single Color LED, 2 V, -30 to 85 degC, 2-Pin SMD (0603), RoHS, Tape and Reel; Manufacturer: Dialight; Power Dissipation: 60W; DELETED: Compliant; Number of  Elements: 1; Viewing Angle: 140deg; Dominant Wave Length: 568nm; Product Depth (mm): 0.8mm; Emitting Color: YellowGreen; Main Category: ChipLED; Product Length (mm): 1.6mm; Forward Voltage: 2.4V; Luminous Intensity: 20mcd; High Brightness: No; Forward Current: 25mA; Test Current (It): 20mA; Shape Type: Rectangular; Reverse Voltage: 5V; Product Height (mm): 0.7mm; Chip Material: GaP
R_LED0-R_LED4 R_LED_ON = Res3: Resistor
SW_1M SW_10k SW_10M SW_100K SW_100M = CMP-011-00006-1: Slide Switch, SPDT, 500 V, -20 to 70 degC, 3-Pin THD, RoHS, Bulk; Manufacturer: E-Switch; Operating Force: 250gf; Contact Current Rating: 200mA; Current Rating: 2dA; Voltage Rating (DC): 30V
U13 = CMP-1633-00060-2: CMOS 8-Bit Priority Encoder, D0016A, TUBE; Manufacturer: Texas Instruments; Channels(#): 1; VCC(Max)(V): 18; Output Drive (IOL/IOH)(Max)(mA): 1.5/-1.5; tpd @ Nom Voltage(Max)(ns): 110; Function: Encoder/Multiplexer; Rating: Catalog; F @ Nom Voltage(Max)(Mhz): 8; Technology Family: CD4000; Schmitt Trigger: No; Configuration: 8：4; Voltage(Nom)(V): 5,10,15; VCC(Min)(V): 3; ICC @ Nom Voltage(Max)(mA): 0.3
U14 = 74VHC238FT: No Description Available; Vendor: Toshiba; SourceLibrary: Toshiba_2019-02-27; Number_devices_in_Package: 1

## Sheet Filters.SchDoc
size A4
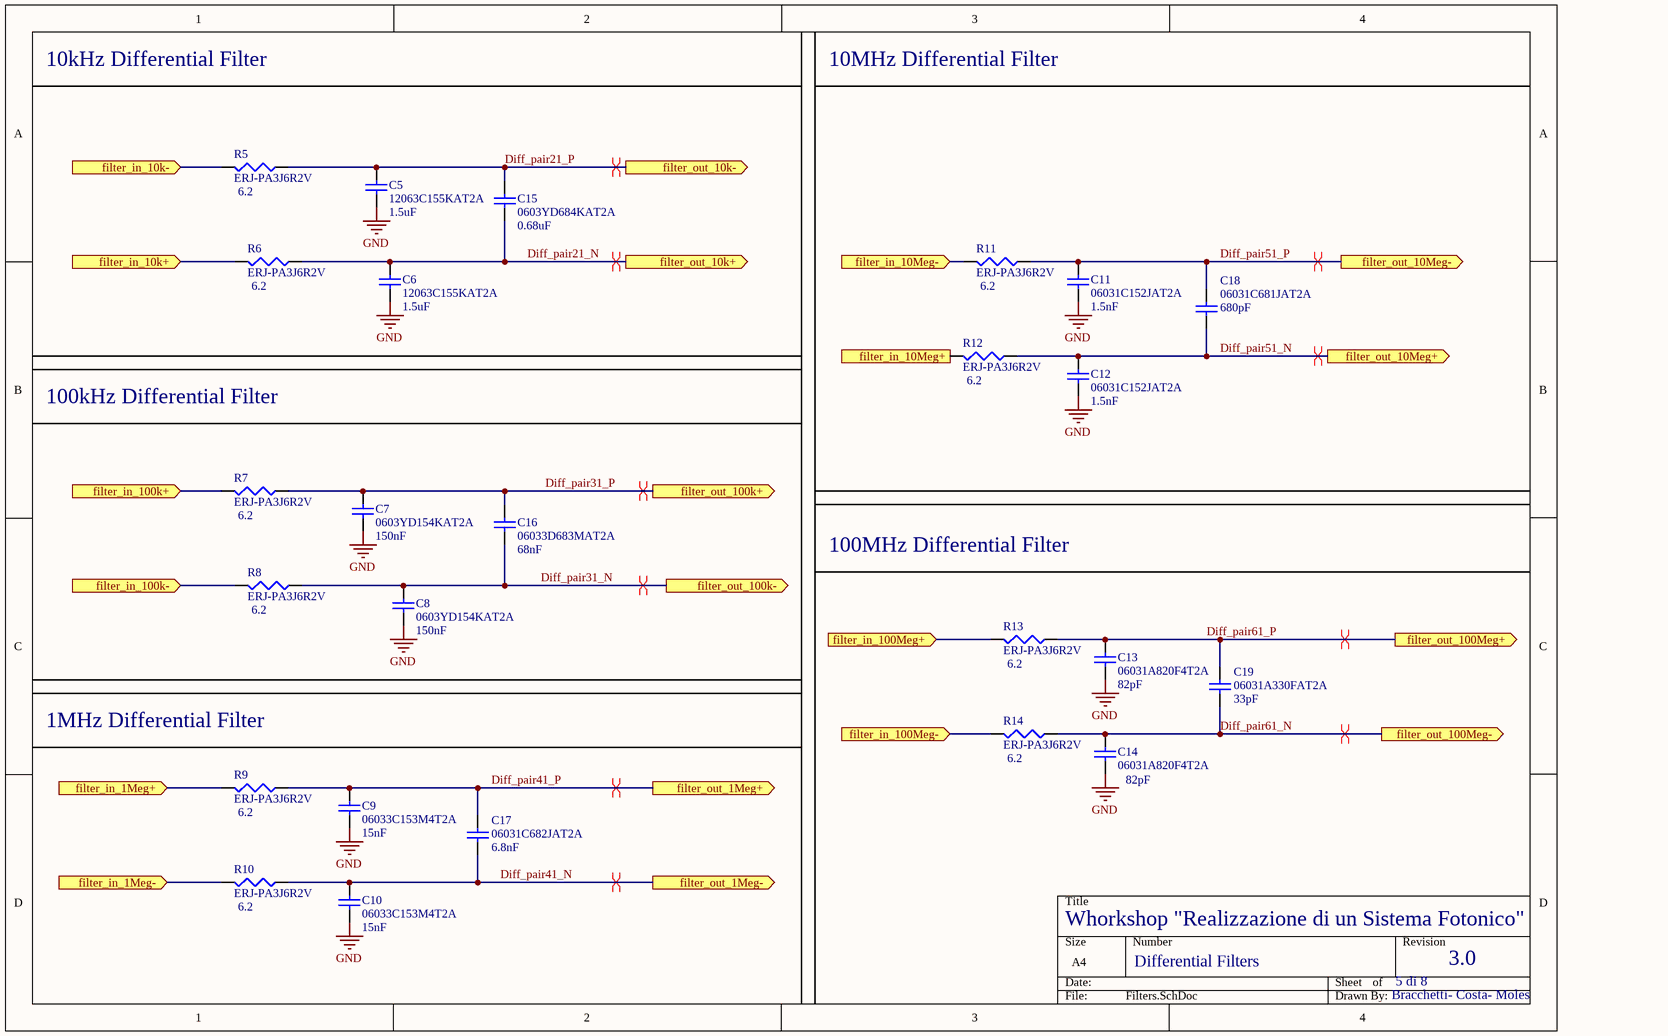
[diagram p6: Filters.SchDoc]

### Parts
C5  12063C155KAT2A  value 1.5uF  [C1206]
C6  12063C155KAT2A  value 1.5uF  [C1206]
C7  0603YD154KAT2A  value 150nF  [1608[0603]]
C8  0603YD154KAT2A  value 150nF  [1608[0603]]
C9  06033C153M4T2A  value 15nF  [1608[0603]]
C10  06033C153M4T2A  value 15nF  [1608[0603]]
C11  06031C152JAT2A  value 1.5nF  [1608[0603]]
C12  06031C152JAT2A  value 1.5nF  [1608[0603]]
C13  06031A820F4T2A  value 82pF  [1608[0603]]
C14  06031A820F4T2A  value 82pF  [1608[0603]]
C15  0603YD684KAT2A  value 0.68uF  [1608[0603]]
C16  06033D683MAT2A  value 68nF  [1608[0603]]
C17  06031C682JAT2A  value 6.8nF  [1608[0603]]
C18  06031C681JAT2A  value 680pF  [1608[0603]]
C19  06031A330FAT2A  value 33pF  [1608[0603]]
R5  ERJ-PA3J6R2V  value 6.2  [1608[0603]]
R6  ERJ-PA3J6R2V  value 6.2  [1608[0603]]
R7  ERJ-PA3J6R2V  value 6.2  [1608[0603]]
R8  ERJ-PA3J6R2V  value 6.2  [1608[0603]]
R9  ERJ-PA3J6R2V  value 6.2  [1608[0603]]
R10  ERJ-PA3J6R2V  value 6.2  [1608[0603]]
R11  ERJ-PA3J6R2V  value 6.2  [1608[0603]]
R12  ERJ-PA3J6R2V  value 6.2  [1608[0603]]
R13  ERJ-PA3J6R2V  value 6.2  [1608[0603]]
R14  ERJ-PA3J6R2V  value 6.2  [1608[0603]]

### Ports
filter_in_1Meg+ (in), filter_in_1Meg- (in), filter_in_10k+ (in), filter_in_10k- (in), filter_in_10Meg+ (in), filter_in_10Meg- (in), filter_in_100k+ (in), filter_in_100k- (in), filter_in_100Meg+ (in), filter_in_100Meg- (in), filter_out_1Meg+ (out), filter_out_1Meg- (out), filter_out_10k+ (out), filter_out_10k- (out), filter_out_10Meg+ (out), filter_out_10Meg- (out), filter_out_100k+ (out), filter_out_100k- (out), filter_out_100Meg+ (out), filter_out_100Meg- (out)

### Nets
GND: C5.1 C6.1 C7.1 C8.1 C9.1 C10.1 C11.1 C12.1 C13.1 C14.1
Diff_pair2_N: R5.2 ; port filter_in_10k-
Diff_pair2_P: R6.2 ; port filter_in_10k+
Diff_pair3_N: R8.2 ; port filter_in_100k-
Diff_pair3_P: R7.2 ; port filter_in_100k+
Diff_pair4_N: R10.2 ; port filter_in_1Meg-
Diff_pair4_P: R9.2 ; port filter_in_1Meg+
Diff_pair5_N: R11.2 ; port filter_in_10Meg-
Diff_pair5_P: R12.2 ; port filter_in_10Meg+
Diff_pair6_N: R14.2 ; port filter_in_100Meg-
Diff_pair6_P: R13.2 ; port filter_in_100Meg+
Diff_pair21_N: C6.2 C15.1 R6.1 ; port filter_out_10k+
Diff_pair21_P: C5.2 C15.2 R5.1 ; port filter_out_10k-
Diff_pair31_N: C8.2 C16.1 R8.1 ; port filter_out_100k-
Diff_pair31_P: C7.2 C16.2 R7.1 ; port filter_out_100k+
Diff_pair41_N: C10.2 C17.1 R10.1 ; port filter_out_1Meg-
Diff_pair41_P: C9.2 C17.2 R9.1 ; port filter_out_1Meg+
Diff_pair51_N: C12.2 C18.1 R12.1 ; port filter_out_10Meg+
Diff_pair51_P: C11.2 C18.2 R11.1 ; port filter_out_10Meg-
Diff_pair61_N: C14.2 C19.1 R14.1 ; port filter_out_100Meg-
Diff_pair61_P: C13.2 C19.2 R13.1 ; port filter_out_100Meg+

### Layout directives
differential pair: Diff_pair21_N, Diff_pair21_P, Diff_pair31_N, Diff_pair31_P, Diff_pair41_N, Diff_pair41_P, Diff_pair51_N, Diff_pair51_P, Diff_pair61_N, Diff_pair61_P

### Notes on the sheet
- 10kHz Differential Filter
- 10MHz Differential Filter
- 100kHz Differential Filter
- 100MHz Differential Filter
- 1MHz Differential Filter
- Whorkshop "Realizzazione di un Sistema Fotonico"
- Differential Filters
- 5 di 8
- 3.0
- Bracchetti- Costa- Moles

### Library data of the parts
C5-C19 = Cap Semi: Capacitor (Semiconductor SIM Model)
R5-R14 = Res3: Resistor

## Sheet OUT_STAGE.SchDoc
size A4
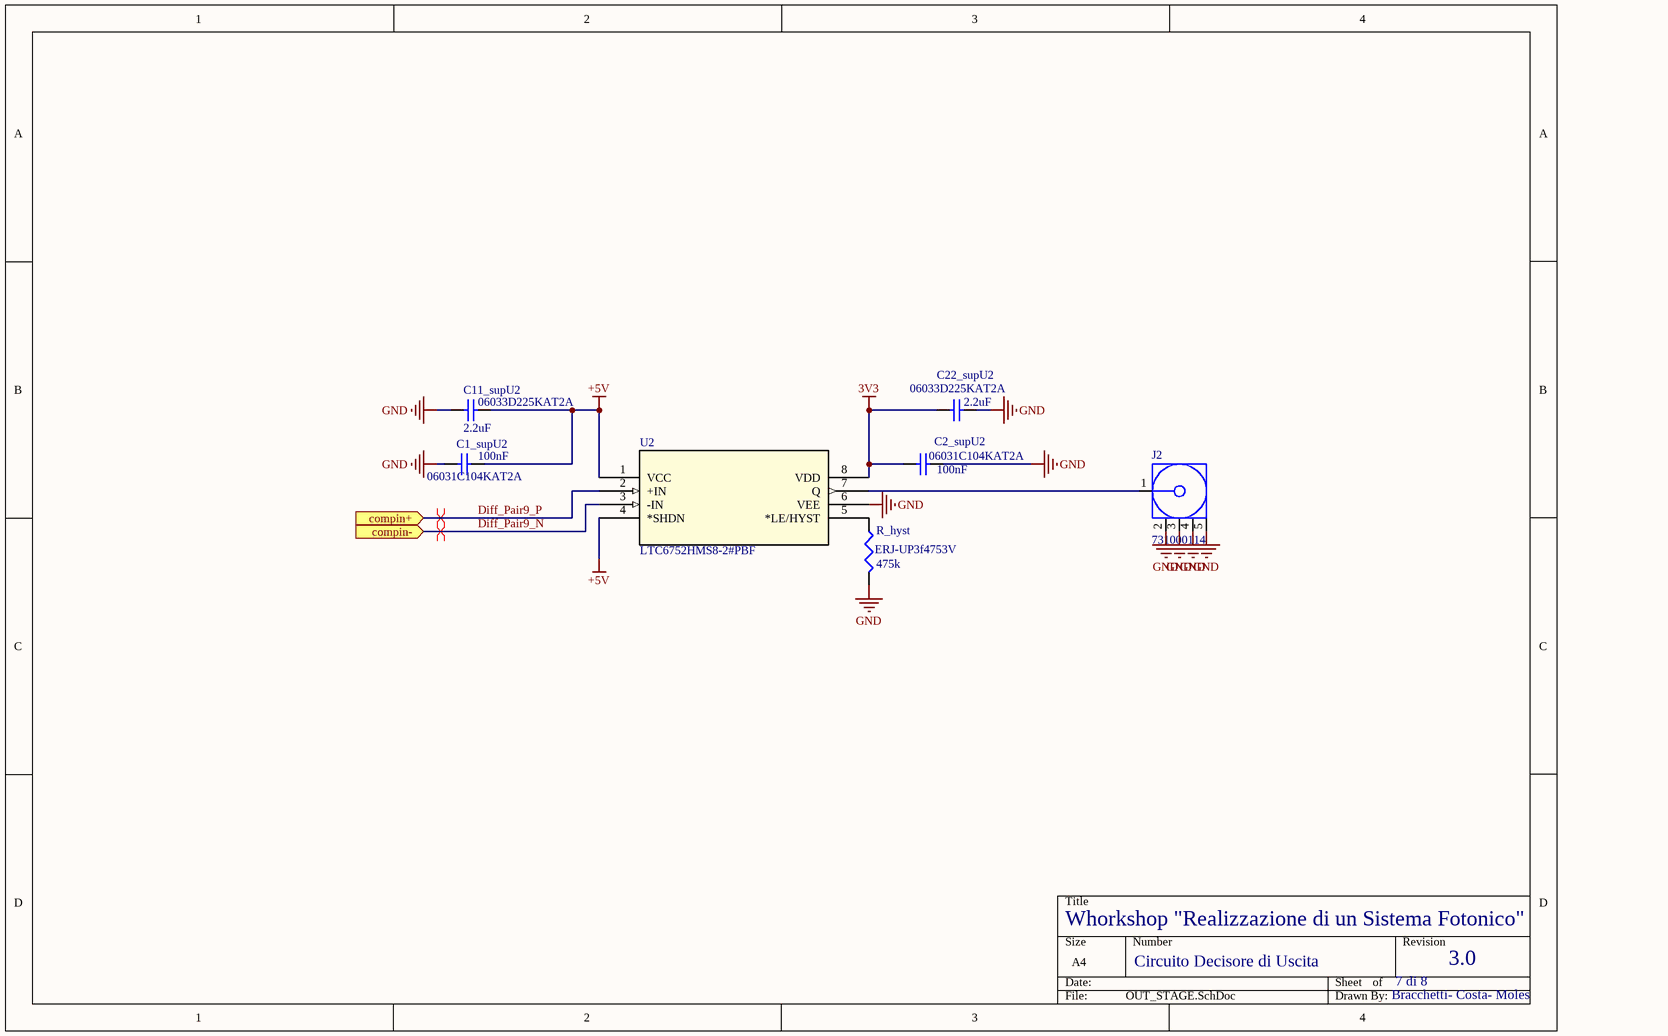
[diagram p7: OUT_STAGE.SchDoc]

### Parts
C1_supU2  06031C104KAT2A  value 100nF  [1608[0603]]
C2_supU2  06031C104KAT2A  value 100nF  [1608[0603]]
C11_supU2  06033D225KAT2A  value 2.2uF  [1608[0603]]
C22_supU2  06033D225KAT2A  value 2.2uF  [1608[0603]]
J2  731000114  [MOLX-731000114_V]
R_hyst  ERJ-UP3f4753V  value 475k  [1608[0603]]
U2  LTC6752HMS8-2#PBF  [MSOP-8_MS_LIT]

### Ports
compin+ (in), compin- (in)

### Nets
3V3: C2_supU2.2 C22_supU2.2 U2.8(VDD)
+5V: C1_supU2.2 C11_supU2.2 U2.1(VCC) U2.4(*SHDN)
GND: C1_supU2.1 C2_supU2.1 C11_supU2.1 C22_supU2.1 J2.2 J2.3 J2.4 J2.5 R_hyst.2 U2.6(VEE)
Diff_Pair9_N: U2.3(-IN) ; port compin-
Diff_Pair9_P: U2.2(+IN) ; port compin+
NetJ2_1: J2.1 U2.7(Q)
NetR_hyst_1: R_hyst.1 U2.5(*LE/HYST)

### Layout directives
differential pair: Diff_Pair9_N, Diff_Pair9_P

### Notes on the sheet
- Whorkshop "Realizzazione di un Sistema Fotonico"
- Circuito Decisore di Uscita
- 7 di 8
- 3.0
- Bracchetti- Costa- Moles

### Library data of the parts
C1_supU2 C2_supU2 C11_supU2 C22_supU2 = Cap Semi: Capacitor (Semiconductor SIM Model)
J2 = CMP-2000-05487-1: as J1 on sheet STAGE _1_2
R_hyst = Res3: Resistor
U2 = LTC6752HMS8-2#PBF: No Description Available; Vendor: Linear Technology; Built_By: EMA_UL_Team; SourceLibrary: LinearTech_2016-05-13_6

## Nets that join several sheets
3V3: SUPPLY_3V3 (Csupout3.2 D3.1 D33.2 U_3V3.3), Selector_stage (15 pins), OUT_STAGE (C2_supU2.2 C22_supU2.2 U2.8)
+2V5: SUPPLY_5V (Csupout4.2 RPG.2 U_2V5.1 U_2V5.2), STAGE _1_2 (7 pins)
+5V: SUPPLY_3V3 (Csupin3.2 D3.2 U_3V3.1), SUPPLY_5V (7 pins), OUT_STAGE (C1_supU2.2 C11_supU2.2 U2.1 U2.4)
+15V: SUPPLY_15V (C15_1.2 C15_2.2 J_supply.1), SUPPLY_5V (Csupin1.2 D1.2 U_5V.1), SWITCH_stage (12 pins)
-2V5: SUPPLY_5V (Csupout5.2 U_-2V5.1 U_-2V5.2), STAGE _1_2 (10 pins)
-15V: SUPPLY_15V (C15_3.1 C15_4.1 J_supply.3), SUPPLY_5V (Csupin2.2 D2.2 U_-5V.2), SWITCH_stage (8 pins)
GND: SUPPLY_15V (5 pins), SUPPLY_3V3 (Csupin3.1 Csupout3.1 D33.1 U_3V3.2), SUPPLY_5V (18 pins), STAGE _1_2 (16 pins), SWITCH_stage (52 pins), Selector_stage (31 pins), Filters (10 pins), OUT_STAGE (10 pins)
Diff_pair1_N: STAGE _1_2 (U1.10), SWITCH_stage (5 pins)
Diff_pair1_P: STAGE _1_2 (U1.11), SWITCH_stage (5 pins)
Diff_pair2_N: SWITCH_stage (U3.10), Filters (R5.2)
Diff_pair2_P: SWITCH_stage (U3.9), Filters (R6.2)
Diff_pair3_N: SWITCH_stage (U4.9), Filters (R8.2)
Diff_pair3_P: SWITCH_stage (U4.10), Filters (R7.2)
Diff_pair4_N: SWITCH_stage (U5.9), Filters (R10.2)
Diff_pair4_P: SWITCH_stage (U5.10), Filters (R9.2)
Diff_pair5_N: SWITCH_stage (U6.10), Filters (R11.2)
Diff_pair5_P: SWITCH_stage (U6.9), Filters (R12.2)
Diff_pair6_N: SWITCH_stage (U7.9), Filters (R14.2)
Diff_pair6_P: SWITCH_stage (U7.10), Filters (R13.2)
Diff_Pair9_N: SWITCH_stage (6 pins), OUT_STAGE (U2.3)
Diff_Pair9_P: SWITCH_stage (6 pins), OUT_STAGE (U2.2)
Diff_pair21_N: SWITCH_stage (U8.10), Filters (C6.2 C15.1 R6.1)
Diff_pair21_P: SWITCH_stage (U8.9), Filters (C5.2 C15.2 R5.1)
Diff_pair31_N: SWITCH_stage (U9.10), Filters (C8.2 C16.1 R8.1)
Diff_pair31_P: SWITCH_stage (U9.9), Filters (C7.2 C16.2 R7.1)
Diff_pair41_N: SWITCH_stage (U10.10), Filters (C10.2 C17.1 R10.1)
Diff_pair41_P: SWITCH_stage (U10.9), Filters (C9.2 C17.2 R9.1)
Diff_pair51_N: SWITCH_stage (U11.10), Filters (C12.2 C18.1 R12.1)
Diff_pair51_P: SWITCH_stage (U11.9), Filters (C11.2 C18.2 R11.1)
Diff_pair61_N: SWITCH_stage (U12.10), Filters (C14.2 C19.1 R14.1)
Diff_pair61_P: SWITCH_stage (U12.9), Filters (C13.2 C19.2 R13.1)
NetR_J15_1: SWITCH_stage (R_J15.1 U8.6 U8.7), Selector_stage (R_LED0.2 U14.11)
NetR_J16_1: SWITCH_stage (R_J16.1 R_J26.1), Selector_stage (R_LED1.2 U14.12)
NetR_J18_2: SWITCH_stage (R_J18.2 R_J24.1), Selector_stage (R_LED2.2 U14.13)
NetR_J20_2: SWITCH_stage (R_J20.2 R_J22.2), Selector_stage (R_LED3.2 U14.14)
NetR_J21_2: SWITCH_stage (R_J21.2 U4.6 U4.7), Selector_stage (R_LED4.2 U14.15)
